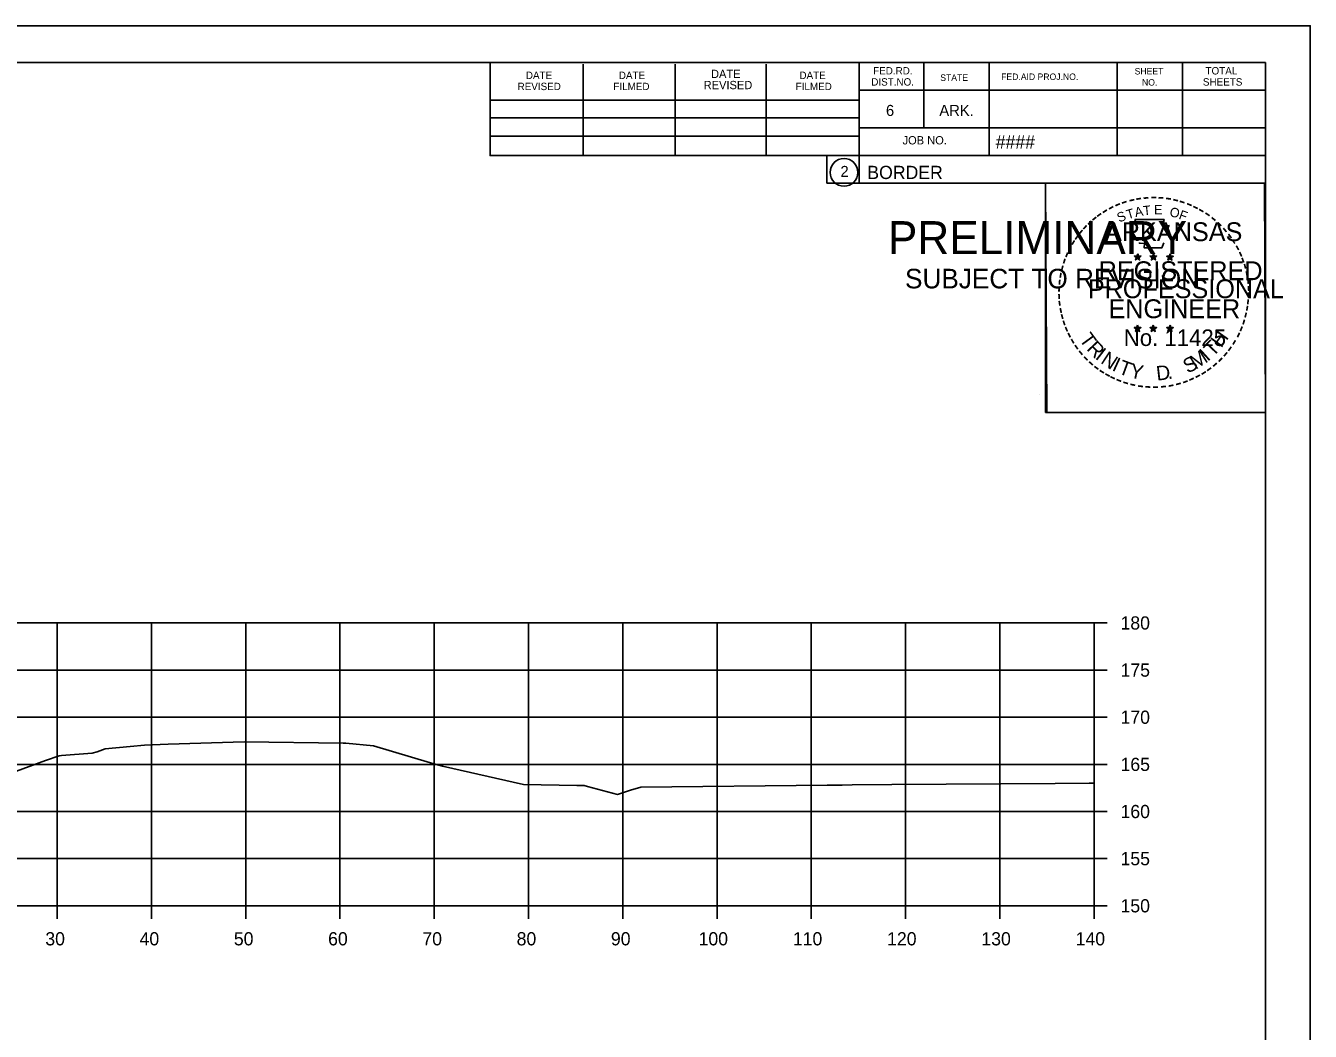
# Model space of a CAD drawing. Extents: x 1368503 to 1373085, y 379840 to 381833.
# Drawn here: x 1372948.7 to 1373085, y 380281.6 to 380388.3 of the extents above; entities that cross this region are included whole.
import ezdxf

# ---------------------------------------------------------------- set-up
doc = ezdxf.new("R2010")
doc.units = 0
for name, color, linetype in [('S_BRIDGE', 7, 'Continuous'), ('S_EDGE_PAVEMENT', 7, 'Continuous'), ('S_LANDSCAPING', 7, 'Continuous'), ('S_MISC_BOUNDARY', 7, 'Continuous'), ('S_MISC_BOUNDARY_ANNOT', 7, 'Continuous'), ('S_PHOTO_CENTERS', 7, 'Continuous'), ('S_PHOTO_NOTES', 7, 'Continuous'), ('S_TRAILS', 7, 'Continuous')]:
    doc.layers.add(name, color=color, linetype=linetype)

msp = doc.modelspace()

# ---------------------------------------------------------------- linework, layer by layer
at = {"layer": 'S_BRIDGE'}
for p, q in [((1372764.08, 380384.41), (1373080.26, 380384.41)), ((1372998, 380374.53), (1372998, 380384.41)), ((1373007.86, 380374.53), (1373007.86, 380384.21)), ((1373017.62, 380374.53), (1373017.62, 380384.21)), ((1373027.3, 380374.53), (1373027.3, 380384.21)), ((1373037.16, 380384.41), (1373037.16, 380371.61)), ((1373044, 380384.41), (1373044, 380377.47)), ((1373050.94, 380384.41), (1373050.94, 380374.53)), ((1373064.52, 380384.41), (1373064.52, 380374.53)), ((1373071.46, 380384.41), (1373071.46, 380374.53)), ((1373080.26, 380178.95), (1373080.26, 380384.41)), ((1373080.26, 380381.47), (1373037.16, 380381.47)), ((1373080.26, 380381.49), (1373080.26, 380381.49)), ((1372998, 380380.39), (1373037.16, 380380.39)), ((1372998, 380378.53), (1373037.16, 380378.53)), ((1373080.26, 380377.47), (1373037.16, 380377.47)), ((1373040.12, 380377.47), (1373080.26, 380377.47)), ((1372998, 380374.53), (1372998, 380376.59)), ((1372998, 380376.59), (1373037.16, 380376.59)), ((1373080.26, 380374.53), (1372998, 380374.53)), ((1373037.16, 380371.61), (1373080.26, 380371.61))]:
    msp.add_line(p, q, dxfattribs=at)
msp.add_circle((1373035.55, 380372.74), 1.47, dxfattribs=at)
at = {"layer": 'S_EDGE_PAVEMENT'}
for p, q in [((1373062.08, 380294.95), (1373062.08, 380324.95)), ((1373063.48, 380324.95), (1373062.08, 380324.95)), ((1373063.48, 380319.95), (1373062.08, 380319.95)), ((1373063.48, 380314.95), (1373062.08, 380314.95)), ((1373063.48, 380309.95), (1373062.08, 380309.95)), ((1373063.48, 380304.95), (1373062.08, 380304.95)), ((1373063.48, 380299.95), (1373062.08, 380299.95)), ((1372782.08, 380294.95), (1373062.08, 380294.95)), ((1372952.08, 380293.55), (1372952.08, 380294.95)), ((1372962.08, 380293.55), (1372962.08, 380294.95)), ((1372972.08, 380293.55), (1372972.08, 380294.95)), ((1372982.08, 380293.55), (1372982.08, 380294.95)), ((1372992.08, 380293.55), (1372992.08, 380294.95)), ((1373002.08, 380293.55), (1373002.08, 380294.95)), ((1373012.08, 380293.55), (1373012.08, 380294.95)), ((1373022.08, 380293.55), (1373022.08, 380294.95)), ((1373032.08, 380293.55), (1373032.08, 380294.95)), ((1373042.08, 380293.55), (1373042.08, 380294.95)), ((1373052.08, 380293.55), (1373052.08, 380294.95)), ((1373062.08, 380293.55), (1373062.08, 380294.95)), ((1373063.48, 380294.95), (1373062.08, 380294.95))]:
    msp.add_line(p, q, dxfattribs=at)
at = {"layer": 'S_LANDSCAPING'}
for p, q in [((1373066.35, 380363.86), (1373066.7, 380363.75)), ((1373066.35, 380363.86), (1373066.6, 380363.82)), ((1373066.35, 380363.86), (1373066.58, 380363.74)), ((1373066.48, 380363.46), (1373066.7, 380363.75)), ((1373066.48, 380363.46), (1373066.61, 380363.7)), ((1373066.48, 380363.46), (1373066.69, 380363.67)), ((1373066.7, 380364.12), (1373066.65, 380363.87)), ((1373066.91, 380363.46), (1373066.69, 380363.67)), ((1373066.7, 380363.75), (1373066.7, 380364.12)), ((1373066.7, 380364.12), (1373066.74, 380363.87)), ((1373067.04, 380363.86), (1373066.7, 380363.75)), ((1373066.91, 380363.46), (1373066.7, 380363.75)), ((1373067.04, 380363.86), (1373066.76, 380363.82)), ((1373066.91, 380363.46), (1373066.77, 380363.75)), ((1373067.04, 380363.86), (1373066.84, 380363.76)), ((1373068.02, 380363.86), (1373068.37, 380363.75)), ((1373068.02, 380363.86), (1373068.27, 380363.82)), ((1373068.02, 380363.86), (1373068.25, 380363.74)), ((1373068.15, 380363.46), (1373068.37, 380363.75)), ((1373068.15, 380363.46), (1373068.28, 380363.7)), ((1373068.15, 380363.46), (1373068.36, 380363.67)), ((1373068.37, 380364.12), (1373068.32, 380363.87)), ((1373068.58, 380363.46), (1373068.36, 380363.67)), ((1373068.37, 380363.75), (1373068.37, 380364.12)), ((1373068.37, 380364.12), (1373068.41, 380363.87)), ((1373068.71, 380363.86), (1373068.37, 380363.75)), ((1373068.58, 380363.46), (1373068.37, 380363.75)), ((1373068.71, 380363.86), (1373068.43, 380363.82)), ((1373068.58, 380363.46), (1373068.44, 380363.75)), ((1373068.71, 380363.86), (1373068.51, 380363.76)), ((1373069.78, 380363.85), (1373070.13, 380363.74)), ((1373069.78, 380363.85), (1373070.03, 380363.81)), ((1373069.78, 380363.85), (1373070.02, 380363.73)), ((1373069.91, 380363.44), (1373070.13, 380363.74)), ((1373069.91, 380363.44), (1373070.04, 380363.69)), ((1373069.91, 380363.44), (1373070.13, 380363.66)), ((1373070.13, 380364.11), (1373070.09, 380363.85)), ((1373070.13, 380363.74), (1373070.13, 380364.11)), ((1373070.13, 380364.11), (1373070.18, 380363.86)), ((1373070.48, 380363.85), (1373070.13, 380363.74)), ((1373070.34, 380363.44), (1373070.13, 380363.74)), ((1373070.34, 380363.44), (1373070.13, 380363.66)), ((1373070.48, 380363.85), (1373070.19, 380363.8)), ((1373070.34, 380363.44), (1373070.21, 380363.74)), ((1373070.48, 380363.85), (1373070.27, 380363.75)), ((1373066.69, 380356.55), (1373066.65, 380356.29)), ((1373066.69, 380356.18), (1373066.69, 380356.55)), ((1373066.69, 380356.55), (1373066.74, 380356.3)), ((1373068.36, 380356.55), (1373068.32, 380356.29)), ((1373068.36, 380356.18), (1373068.36, 380356.55)), ((1373068.36, 380356.55), (1373068.41, 380356.3)), ((1373070.13, 380356.54), (1373070.09, 380356.28)), ((1373070.13, 380356.17), (1373070.13, 380356.54)), ((1373070.13, 380356.54), (1373070.18, 380356.29)), ((1373066.34, 380356.29), (1373066.69, 380356.18)), ((1373066.34, 380356.29), (1373066.6, 380356.25)), ((1373066.34, 380356.29), (1373066.58, 380356.17)), ((1373066.48, 380355.88), (1373066.69, 380356.18)), ((1373066.48, 380355.88), (1373066.6, 380356.13)), ((1373066.48, 380355.88), (1373066.69, 380356.1)), ((1373067.04, 380356.29), (1373066.69, 380356.18)), ((1373066.9, 380355.88), (1373066.69, 380356.18)), ((1373066.9, 380355.88), (1373066.69, 380356.1)), ((1373067.04, 380356.29), (1373066.75, 380356.24)), ((1373066.9, 380355.88), (1373066.77, 380356.17)), ((1373067.04, 380356.29), (1373066.83, 380356.19)), ((1373068.01, 380356.29), (1373068.36, 380356.18)), ((1373068.01, 380356.29), (1373068.26, 380356.25)), ((1373068.01, 380356.29), (1373068.25, 380356.17)), ((1373068.14, 380355.88), (1373068.36, 380356.18)), ((1373068.14, 380355.88), (1373068.27, 380356.13)), ((1373068.14, 380355.88), (1373068.36, 380356.1)), ((1373068.71, 380356.29), (1373068.36, 380356.18)), ((1373068.57, 380355.88), (1373068.36, 380356.18)), ((1373068.57, 380355.88), (1373068.36, 380356.1)), ((1373068.71, 380356.29), (1373068.42, 380356.24)), ((1373068.57, 380355.88), (1373068.44, 380356.17)), ((1373068.71, 380356.29), (1373068.5, 380356.19)), ((1373069.78, 380356.28), (1373070.13, 380356.17)), ((1373069.78, 380356.28), (1373070.03, 380356.24)), ((1373069.78, 380356.28), (1373070.02, 380356.16)), ((1373069.91, 380355.87), (1373070.13, 380356.17)), ((1373069.91, 380355.87), (1373070.04, 380356.12)), ((1373069.91, 380355.87), (1373070.13, 380356.09)), ((1373070.47, 380356.28), (1373070.13, 380356.17)), ((1373070.34, 380355.87), (1373070.13, 380356.17)), ((1373070.34, 380355.87), (1373070.13, 380356.09)), ((1373070.47, 380356.28), (1373070.19, 380356.23)), ((1373070.34, 380355.87), (1373070.2, 380356.16)), ((1373070.47, 380356.28), (1373070.27, 380356.18))]:
    msp.add_line(p, q, dxfattribs=at)
for points in [[(1373066.39, 380367.74), (1373066.66, 380366.92)], [(1373069.9, 380366.82), (1373070.04, 380367.1), (1373069.36, 380367.08), (1373069.5, 380367.74), (1373066.39, 380367.74)], [(1373066.88, 380365.32), (1373066.88, 380365.23), (1373067.44, 380365.21), (1373067.39, 380364.74), (1373069.26, 380364.74), (1373069.46, 380365.28)], [(1373066.7, 380364.12), (1373066.91, 380363.46), (1373066.35, 380363.86), (1373067.04, 380363.86), (1373066.48, 380363.46), (1373066.7, 380364.12)], [(1373068.37, 380364.12), (1373068.58, 380363.46), (1373068.02, 380363.86), (1373068.71, 380363.86), (1373068.15, 380363.46), (1373068.37, 380364.12)], [(1373070.13, 380364.11), (1373070.34, 380363.44), (1373069.78, 380363.85), (1373070.48, 380363.85), (1373069.91, 380363.44), (1373070.13, 380364.11)], [(1373066.69, 380356.55), (1373066.9, 380355.88), (1373066.34, 380356.29), (1373067.04, 380356.29), (1373066.48, 380355.88), (1373066.69, 380356.55)], [(1373068.36, 380356.55), (1373068.57, 380355.88), (1373068.01, 380356.29), (1373068.71, 380356.29), (1373068.14, 380355.88), (1373068.36, 380356.55)], [(1373070.13, 380356.54), (1373070.34, 380355.87), (1373069.78, 380356.28), (1373070.47, 380356.28), (1373069.91, 380355.87), (1373070.13, 380356.54)]]:
    msp.add_lwpolyline(points, dxfattribs=at)
for centre, radius in [((1373066.69, 380363.75), 0.172), ((1373066.69, 380363.75), 0.145), ((1373066.69, 380363.75), 0.116), ((1373066.69, 380363.75), 0.0991), ((1373066.69, 380363.75), 0.0747), ((1373066.69, 380363.75), 0.0495), ((1373066.69, 380363.75), 0.0296), ((1373068.36, 380363.75), 0.172), ((1373068.36, 380363.75), 0.145), ((1373068.36, 380363.75), 0.116), ((1373068.36, 380363.75), 0.0991), ((1373068.36, 380363.75), 0.0747), ((1373068.36, 380363.75), 0.0495), ((1373068.36, 380363.75), 0.0296), ((1373070.13, 380363.74), 0.172), ((1373070.13, 380363.74), 0.145), ((1373070.13, 380363.74), 0.116), ((1373070.13, 380363.74), 0.0991), ((1373070.13, 380363.74), 0.0747), ((1373070.13, 380363.74), 0.0495), ((1373070.13, 380363.74), 0.0296), ((1373066.69, 380356.18), 0.172), ((1373066.69, 380356.18), 0.145), ((1373066.69, 380356.18), 0.116), ((1373066.69, 380356.18), 0.0991), ((1373066.69, 380356.18), 0.0747), ((1373066.69, 380356.18), 0.0495), ((1373066.69, 380356.18), 0.0296), ((1373068.36, 380356.18), 0.172), ((1373068.36, 380356.18), 0.145), ((1373068.36, 380356.18), 0.116), ((1373068.36, 380356.18), 0.0991), ((1373068.36, 380356.18), 0.0747), ((1373068.36, 380356.18), 0.0495), ((1373068.36, 380356.18), 0.0296), ((1373070.13, 380356.17), 0.172), ((1373070.13, 380356.17), 0.145), ((1373070.13, 380356.17), 0.116), ((1373070.13, 380356.17), 0.0991), ((1373070.13, 380356.17), 0.0747), ((1373070.13, 380356.17), 0.0495), ((1373070.13, 380356.17), 0.0296)]:
    msp.add_circle(centre, radius, dxfattribs=at)
at = {"layer": 'S_MISC_BOUNDARY'}
msp.add_lwpolyline([(1372940.89, 380306.71), (1372950.83, 380310.36), (1372952.28, 380310.87), (1372952.55, 380310.9), (1372955.79, 380311.13), (1372956.31, 380311.29), (1372957.18, 380311.6), (1372959.84, 380311.83), (1372961.33, 380312), (1372963.84, 380312.09), (1372971.93, 380312.35), (1372982.42, 380312.2), (1372982.66, 380312.19), (1372982.69, 380312.19), (1372985.65, 380311.91), (1372991.69, 380310.12), (1372992.43, 380309.9), (1372992.95, 380309.77), (1373001.54, 380307.83), (1373007.19, 380307.71), (1373007.97, 380307.7), (1373008.34, 380307.6), (1373011.53, 380306.76), (1373012.91, 380307.2), (1373014, 380307.54), (1373033.76, 380307.75), (1373035.34, 380307.76), (1373036.4, 380307.77), (1373040.63, 380307.8), (1373057.95, 380307.92), (1373061.55, 380307.95), (1373062.08, 380307.96)], dxfattribs=at)
at = {"layer": 'S_PHOTO_CENTERS'}
for p, q in [((1372782.08, 380324.95), (1373062.08, 380324.95)), ((1372952.08, 380294.95), (1372952.08, 380324.95)), ((1372962.08, 380294.95), (1372962.08, 380324.95)), ((1372972.08, 380294.95), (1372972.08, 380324.95)), ((1372982.08, 380294.95), (1372982.08, 380324.95)), ((1372992.08, 380294.95), (1372992.08, 380324.95)), ((1373002.08, 380294.95), (1373002.08, 380324.95)), ((1373012.08, 380294.95), (1373012.08, 380324.95)), ((1373022.08, 380294.95), (1373022.08, 380324.95)), ((1373032.08, 380294.95), (1373032.08, 380324.95)), ((1373042.08, 380294.95), (1373042.08, 380324.95)), ((1373052.08, 380294.95), (1373052.08, 380324.95)), ((1373062.08, 380294.95), (1373062.08, 380324.95)), ((1372782.08, 380319.95), (1373062.08, 380319.95)), ((1372782.08, 380314.95), (1373062.08, 380314.95)), ((1372782.08, 380309.95), (1373062.08, 380309.95)), ((1372782.08, 380304.95), (1373062.08, 380304.95)), ((1372782.08, 380299.95), (1373062.08, 380299.95)), ((1372782.08, 380294.95), (1373062.08, 380294.95))]:
    msp.add_line(p, q, dxfattribs=at)
at = {"layer": 'S_PHOTO_NOTES'}
for p, q in [((1372751.68, 380388.3), (1373085.01, 380388.3)), ((1373056.3, 380349.15), (1373056.3, 380349.15))]:
    msp.add_line(p, q, dxfattribs=at)
for points in [[(1372751.67, 380388.3), (1373085.01, 380388.3), (1373085.01, 380174.97), (1372751.67, 380174.97)], [(1372998, 380384.41), (1372998, 380374.53), (1373033.73, 380374.53), (1373033.73, 380371.61), (1373056.93, 380371.61), (1373056.93, 380347.28), (1373080.26, 380347.28), (1373080.26, 380178.95), (1372764.08, 380178.95), (1372764.08, 380384.41)], [(1373056.93, 380371.61), (1373080.14, 380371.61), (1373080.26, 380347.28), (1373057.05, 380347.28)]]:
    msp.add_lwpolyline(points, close=True, dxfattribs=at)

# ---------------------------------------------------------------- texts
at = {"layer": 'S_BRIDGE'}
for s, height, p in [('FED.RD.', 0.782, (1373038.64, 380383.13)), ('SHEET', 0.684, (1373066.38, 380383.13)), ('TOTAL', 0.782, (1373073.9, 380383.13)), ('DATE', 0.782, (1373001.8, 380382.65)), ('DATE', 0.782, (1373011.66, 380382.65)), ('REVISED', 0.879, (1373020.66, 380381.57)), ('DATE', 0.879, (1373021.44, 380382.75)), ('DATE', 0.782, (1373030.82, 380382.65)), ('DIST.NO.', 0.782, (1373038.44, 380381.95)), ('STATE', 0.684, (1373045.76, 380382.45)), ('FED.AID PROJ.NO.', 0.684, (1373052.22, 380382.55)), ('NO.', 0.684, (1373067.16, 380381.95)), ('SHEETS', 0.782, (1373073.62, 380381.95)), ('REVISED', 0.782, (1373000.92, 380381.47)), ('FILMED', 0.782, (1373011.08, 380381.47)), ('FILMED', 0.782, (1373030.42, 380381.47)), ('6', 1.17, (1373040, 380378.73)), ('ARK.', 1.172, (1373045.66, 380378.73)), ('JOB NO.', 0.879, (1373041.76, 380375.71)), ('####', 1.4, (1373051.64, 380375.27)), ('2', 1.17, (1373035.17, 380372.26)), ('BORDER', 1.4, (1373038.02, 380372.04))]:
    msp.add_text(s, height=height, rotation=360, dxfattribs=at).set_placement(p)
at = {"layer": 'S_LANDSCAPING'}
for s, height, rotation, p in [('-', 1.6, 10.2193, (1373066.56, 380369.27)), ('-', 1.6, 5.8968, (1373067.29, 380369.38)), ('-', 1.6, 0.1862, (1373068.06, 380369.45)), ('-', 1.6, 357.743, (1373068.79, 380369.44)), ('-', 1.6, 352.1617, (1373069.53, 380369.39)), ('-', 1.6, 34.0636, (1373063.27, 380367.91)), ('-', 1.6, 28.7918, (1373063.87, 380368.28)), ('-', 1.6, 24.3072, (1373064.5, 380368.6)), ('-', 1.6, 19.1761, (1373065.14, 380368.87)), ('T', 1, 16.4036, (1373065.66, 380367.75)), ('-', 1.6, 13.6301, (1373065.89, 380369.11)), ('A', 1, 11.2132, (1373066.48, 380368)), ('T', 1, 6.0228, (1373067.33, 380368.17)), ('E', 1, 0.8323, (1373068.44, 380368.28)), ('O', 1, 350.4515, (1373070.04, 380368.07)), ('-', 1.6, 347.2049, (1373070.25, 380369.27)), ('F', 1, 340.0707, (1373070.99, 380367.84)), ('-', 1.6, 342.3362, (1373070.89, 380369.12)), ('-', 1.6, 337.8551, (1373071.62, 380368.89)), ('-', 1.6, 334.1211, (1373072.25, 380368.62)), ('-', 1.6, 329.6409, (1373072.83, 380368.34)), ('-', 1.6, 42.9622, (1373061.78, 380366.72)), ('-', 1.6, 38.9507, (1373062.22, 380367.14)), ('-', 1.6, 36.2317, (1373062.69, 380367.52)), ('ARKANSAS', 2, 360, (1373063.24, 380365.45)), ('S', 1, 21.594, (1373064.74, 380367.42)), ('-', 1.6, 325.8627, (1373073.47, 380367.98)), ('-', 1.6, 320.5297, (1373074.08, 380367.55)), ('-', 1.6, 315.5786, (1373074.68, 380367.06)), ('-', 1.6, 54.2325, (1373060.52, 380365.19)), ('-', 1.6, 50.6142, (1373060.93, 380365.76)), ('-', 1.6, 48.423, (1373061.34, 380366.25)), ('-', 1.6, 309.8797, (1373075.25, 380366.51)), ('-', 1.6, 306.6522, (1373075.78, 380365.91)), ('-', 1.6, 62.8713, (1373059.88, 380364.05)), ('-', 1.6, 58.0706, (1373060.2, 380364.67)), ('-', 1.4, 303.6753, (1373076.26, 380365.34)), ('-', 1.6, 299.6684, (1373076.58, 380364.74)), ('-', 1.6, 72.3945, (1373059.4, 380362.81)), ('-', 1.6, 67.7743, (1373059.62, 380363.44)), ('REGISTERED', 2, 360, (1373062.56, 380361.31)), ('DWB', 0.01, 360, (1373066.68, 380363.75)), ('DWB', 0.01, 360, (1373068.35, 380363.75)), ('DWB', 0.01, 360, (1373070.12, 380363.74)), ('-', 1.6, 294.6628, (1373076.91, 380364.13)), ('-', 1.6, 290.5728, (1373077.16, 380363.55)), ('-', 1.6, 81.2013, (1373059.08, 380361.38)), ('-', 1.6, 75.461, (1373059.21, 380362.1)), ('-', 1.6, 285.1233, (1373077.4, 380362.97)), ('-', 1.6, 280.5493, (1373077.6, 380362.23)), ('-', 1.6, 89.0622, (1373058.97, 380359.99)), ('-', 1.6, 85.1863, (1373059, 380360.69)), ('PROFESSIONAL', 2, 360, (1373061.41, 380359.4)), ('-', 1.6, 276.5962, (1373077.76, 380361.46)), ('-', 1.6, 274.3301, (1373077.82, 380360.74)), ('-', 1.6, 94.1959, (1373059.01, 380359.27)), ('ENGINEER', 2, 360, (1373063.6, 380357.28)), ('-', 1.6, 263.5172, (1373077.83, 380359.44)), ('-', 1.6, 269.9407, (1373077.85, 380360.1)), ('-', 1.6, 98.9479, (1373059.08, 380358.6)), ('-', 1.6, 101.7149, (1373059.22, 380357.87)), ('-', 1.6, 255.7626, (1373077.65, 380358.11)), ('-', 1.6, 260.9953, (1373077.76, 380358.78)), ('-', 1.6, 105.4578, (1373059.38, 380357.27)), ('-', 1.6, 109.0874, (1373059.59, 380356.64)), ('-', 1.6, 247.8887, (1373077.25, 380356.71)), ('-', 1.6, 252.8681, (1373077.47, 380357.39)), ('-', 1.6, 114.0643, (1373059.85, 380356.04)), ('-', 1.6, 115.7289, (1373060.15, 380355.43)), ('-', 1.6, 120.4471, (1373060.51, 380354.84)), ('T', 1.54, 306.0406, (1373060.45, 380355.02)), ('No. 11425', 1.757, 360, (1373065.23, 380354.33)), ('DWB', 0.01, 360, (1373066.68, 380356.18)), ('DWB', 0.01, 360, (1373068.35, 380356.18)), ('DWB', 0.01, 360, (1373070.11, 380356.17)), ('H', 1.54, 54.6088, (1373075.57, 380354.05)), ('-', 1.6, 244.6197, (1373076.99, 380356.08)), ('-', 1.6, 125.8934, (1373060.91, 380354.28)), ('-', 1.6, 130.7181, (1373061.37, 380353.73)), ('R', 1.54, 314.005, (1373061.21, 380353.97)), ('I', 1.54, 321.9694, (1373062.11, 380353.04)), ('N', 1.54, 326.5002, (1373062.68, 380352.57)), ('M', 1.54, 32.6563, (1373072.84, 380351.79)), ('I', 1.54, 42.1136, (1373074.12, 380352.63)), ('T', 1.54, 46.6444, (1373074.68, 380353.11)), ('-', 1.6, 231.2538, (1373075.76, 380354.11)), ('-', 1.6, 233.8452, (1373076.19, 380354.68)), ('-', 1.6, 239.0712, (1373076.59, 380355.33)), ('-', 1.6, 134.2238, (1373061.89, 380353.18)), ('-', 1.6, 138.9338, (1373062.42, 380352.72)), ('I', 1.54, 335.3603, (1373063.89, 380351.78)), ('T', 1.54, 339.8912, (1373064.55, 380351.45)), ('Y', 1.54, 347.8556, (1373065.77, 380351.01)), ('S', 1.54, 26.9312, (1373072, 380351.38)), ('-', 1.6, 221.0851, (1373074.76, 380353.04)), ('-', 1.6, 225.7653, (1373075.28, 380353.55)), ('-', 1.6, 144.6463, (1373062.97, 380352.31)), ('-', 1.6, 148.0898, (1373063.53, 380351.94)), ('-', 1.6, 151.5704, (1373064.11, 380351.62)), ('-', 1.6, 154.6002, (1373064.63, 380351.37)), ('D', 1.54, 6.3969, (1373068.75, 380350.65)), ('.', 1.54, 13.7642, (1373069.94, 380350.78)), ('-', 1.6, 204.2516, (1373072.49, 380351.52)), ('-', 1.6, 207.3568, (1373073.12, 380351.84)), ('-', 1.6, 212.2491, (1373073.68, 380352.18)), ('-', 1.6, 215.7363, (1373074.21, 380352.57)), ('-', 1.6, 158.5612, (1373065.26, 380351.12)), ('-', 1.6, 162.7983, (1373065.95, 380350.9)), ('-', 1.6, 167.5555, (1373066.66, 380350.74)), ('-', 1.6, 173.1155, (1373067.43, 380350.63)), ('-', 1.6, 176.5183, (1373068.18, 380350.58)), ('-', 1.6, 181.5918, (1373068.92, 380350.59)), ('-', 1.6, 185.8167, (1373069.73, 380350.67)), ('-', 1.6, 191.2858, (1373070.47, 380350.8)), ('-', 1.6, 195.4743, (1373071.2, 380351)), ('-', 1.6, 200.7184, (1373071.88, 380351.24))]:
    msp.add_text(s, height=height, rotation=rotation, dxfattribs=at).set_placement(p)
at = {"layer": 'S_MISC_BOUNDARY_ANNOT'}
for s, height, p in [('PRELIMINARY', 3.5, (1373040.21, 380364.07)), ('DWB', 0.01, (1373040.96, 380365.92)), ('SUBJECT TO REVISION', 2.0751, (1373042.02, 380360.44))]:
    msp.add_text(s, height=height, rotation=360, dxfattribs=at).set_placement(p)
at = {"layer": 'S_TRAILS'}
for s, p in [('180', (1373064.88, 380324.25)), ('175', (1373064.88, 380319.25)), ('170', (1373064.88, 380314.25)), ('165', (1373064.88, 380309.25)), ('160', (1373064.88, 380304.25)), ('155', (1373064.88, 380299.25)), ('150', (1373064.88, 380294.25)), ('30', (1372950.82, 380290.75)), ('40', (1372960.82, 380290.75)), ('50', (1372970.82, 380290.75)), ('60', (1372980.82, 380290.75)), ('70', (1372990.82, 380290.75)), ('80', (1373000.82, 380290.75)), ('90', (1373010.82, 380290.75)), ('100', (1373020.12, 380290.75)), ('110', (1373030.12, 380290.75)), ('120', (1373040.12, 380290.75)), ('130', (1373050.12, 380290.75)), ('140', (1373060.12, 380290.75))]:
    msp.add_text(s, height=1.4, dxfattribs=at).set_placement(p)

doc.saveas('drawing.dxf')
